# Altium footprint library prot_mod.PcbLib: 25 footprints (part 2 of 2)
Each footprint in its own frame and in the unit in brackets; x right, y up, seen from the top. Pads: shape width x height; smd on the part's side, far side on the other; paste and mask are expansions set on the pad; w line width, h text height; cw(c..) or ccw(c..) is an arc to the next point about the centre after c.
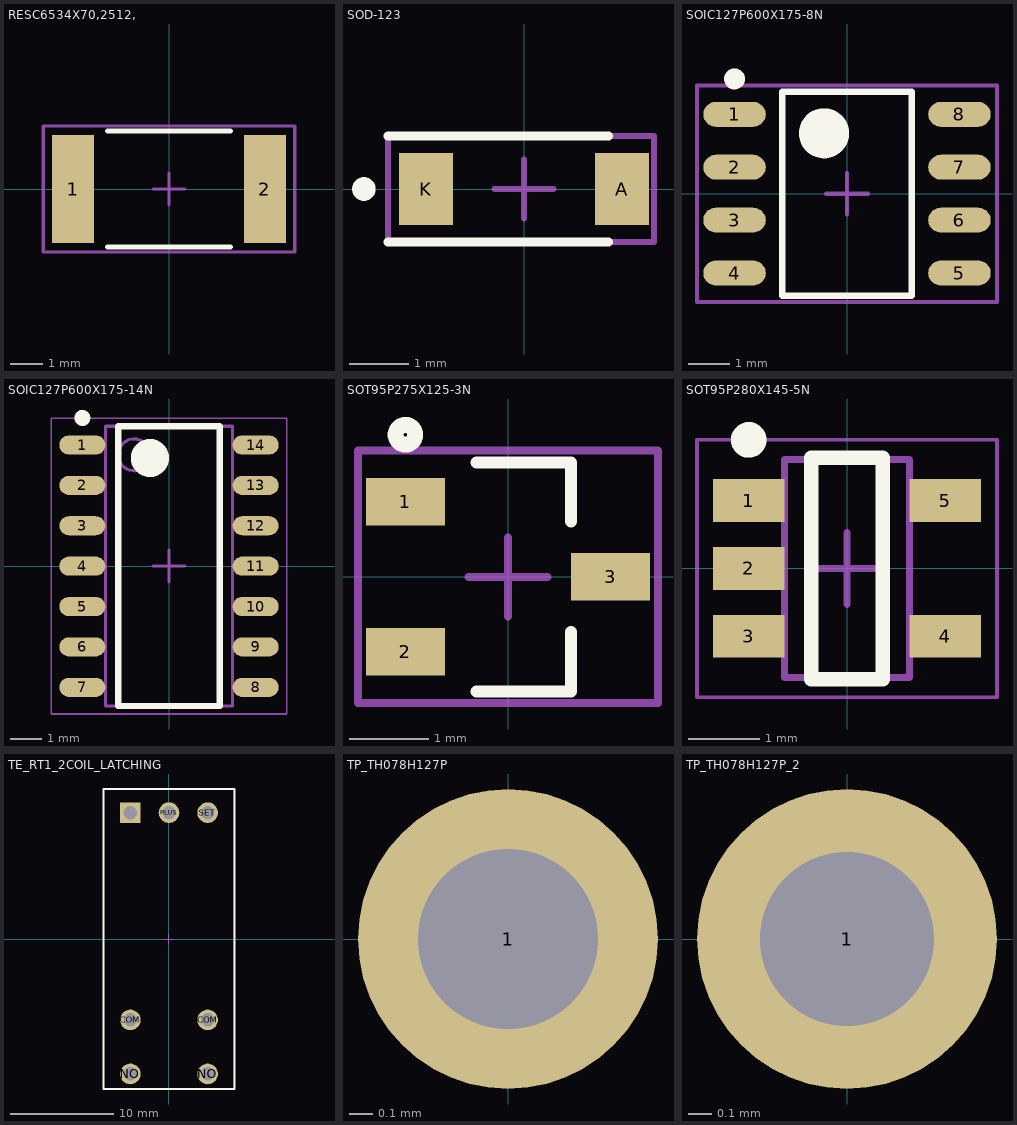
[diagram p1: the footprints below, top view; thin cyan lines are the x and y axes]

## RESC6534X70,2512, [mm]
pads (2):
  rect 1.3x3.35 smd: 1(-2.975,0) 2(2.975,0)
Top Overlay:
  lines w0.153: -1.9,-1.8 1.9,-1.8 ; -1.9,1.8 1.9,1.8
Top Component Center:
  lines w0.1: -0.5,0 0.5,0 ; 0,-0.5 0,0.5
Top Courtyard:
  lines w0.1: -3.9,-1.95 -3.9,1.95 3.9,1.95 3.9,-1.95 -3.9,-1.95
3D body: height 0.7, standoff 0, extent -2.65,-1.65 2.65,1.65
3D body: height 0.7, standoff 0, extent -3.25,-1.65 -2.65,1.65
3D body: height 0.7, standoff 0, extent 2.65,-1.65 3.25,1.65

## SOD-123 [mil]
pads (2):
  rect 36x48 smd: A(65.35,0) K(-65.35,0)
Top Overlay:
  circle w7.87: c-106.79,0 r3.94
  lines w6.02: -90.77,-35.43 56.3,-35.43 ; -90.77,35.43 56.3,35.43
Top Component Center:
  lines w3.94: -19.68,0 19.68,0 ; 0,-19.68 0,19.68
Top Courtyard:
  lines w3.94: -90.77,-35.43 86.61,-35.43 86.61,35.43 -90.77,35.43 -90.77,-35.43
3D body "SOD-123.STEP": height 53.19, standoff 0, extent -72.83,-31.49 72.84,31.5

## SOIC127P600X175-8N [mm]
pads (8):
  oval 1.5x0.6 smd: 1(-2.7,1.905) 2(-2.7,0.635) 3(-2.7,-0.635) 4(-2.7,-1.905) 5(2.7,-1.905) 6(2.7,-0.635) 7(2.7,0.635) 8(2.7,1.905)
Top Overlay:
  circle w0.25: c-2.7,2.755 r0.125
  circle w0.6: c-0.55,1.45 r0.3
  lines w0.153: -1.55,-2.45 -1.55,2.45 1.55,2.45 1.55,-2.45 -1.55,-2.45
Top Component Center:
  lines w0.1: -0.5,0 0.5,0 ; 0,-0.5 0,0.5
Top Courtyard:
  lines w0.1: -3.6,-2.6 -3.6,2.6 3.6,2.6 3.6,-2.6 -3.6,-2.6
3D body "SOIC127P600X175-8N.step": height 1.75, standoff 0, extent -3,-2.45 3,2.45

## SOIC127P600X175-14N [mm]
pads (14):
  oval 1.45x0.6 smd: 1(-2.725,3.81) 2(-2.725,2.54) 3(-2.725,1.27) 4(-2.725,0) 5(-2.725,-1.27) 6(-2.725,-2.54) 7(-2.725,-3.81) 8(2.725,-3.81) 9(2.725,-2.54) 10(2.725,-1.27) 11(2.725,0) 12(2.725,1.27) 13(2.725,2.54) 14(2.725,3.81)
Top Overlay:
  circle w0.6: c-0.6,3.4 r0.3
  circle w0.25: c-2.725,4.66 r0.125
  lines w0.2: -1.6,-4.4 1.6,-4.4 1.6,4.4 -1.6,4.4 -1.6,-4.4
Top Component Center:
  lines w0.1: -0.5,0 0.5,0 ; 0,-0.5 0,0.5
Top Assembly:
  circle w0.1: c-1.1,3.5 r0.5
  lines w0.1: -2,-4.4 2,-4.4 2,4.4 -2,4.4 -2,-4.4
Top Courtyard:
  lines w0.05: -3.7,-4.65 3.7,-4.65 3.7,4.65 -3.7,4.65 -3.7,-4.65
3D body: height 1.75, standoff 0.1, extent -2,-4.4 2,4.4

## SOT95P275X125-3N [mm]
pads (3):
  rect 1x0.6 smd: 1(-1.3,0.95) 2(-1.3,-0.95) 3(1.3,0)
Top Overlay:
  circle w0.2: c-1.3,1.8 r0.125
  lines w0.153: -0.4,-1.45 0.8,-1.45 0.8,-0.7 ; -0.4,1.45 0.8,1.45 0.8,0.7
Top Component Center:
  lines w0.1: -0.5,0 0.5,0 ; 0,-0.5 0,0.5
Top Courtyard:
  lines w0.1: -1.9,-1.6 1.9,-1.6 1.9,1.6 -1.9,1.6 -1.9,-1.6
3D body "SOT95P275X125-3N.step": height 1.25, standoff 0, extent -1.375,-1.45 1.375,1.45

## SOT95P280X145-5N [mm]
pads (5):
  rect 1x0.6 smd: 1(-1.375,0.95) 2(-1.375,0) 3(-1.375,-0.95) 4(1.375,-0.95) 5(1.375,0.95)
Top Overlay:
  circle w0.25: c-1.375,1.8 r0.125
  lines w0.2: -0.5,-1.55 -0.5,1.55 0.5,1.55 0.5,-1.55 -0.5,-1.55
Top Component Center:
  lines w0.1: -0.5,0 0.5,0 ; 0,-0.5 0,0.5
Top Assembly:
  lines w0.1: -0.875,-1.525 0.875,-1.525 0.875,1.525 -0.875,1.525 -0.875,-1.525
Top Courtyard:
  lines w0.05: -2.1,-1.8 2.1,-1.8 2.1,1.8 -2.1,1.8 -2.1,-1.8
3D body: height 1.45, standoff 0, extent -0.875,-1.525 0.875,1.525

## TE_RT1_2COIL_LATCHING [mm]
pads (7):
  round 2 hole 1.3: COM(-3.75,-7.85) COM(3.75,-7.85) NO(-3.75,-13.09) NO(3.75,-13.09) PLUS(0,12.25) SET(3.75,12.25)
  rect 2x2 hole 1.3: RESET(-3.75,12.25)
Top Overlay:
  lines w0.153: -6.35,-14.55 6.35,-14.55 6.35,14.55 -1.05,14.55 -6.35,14.55 -6.35,-14.55
Top Component Center:
  lines w0.1: -0.5,0 0.5,0 ; 0,-0.5 0,0.5
Top Courtyard:
  lines w0.1: -6.35,-14.55 -6.35,14.55 -1.05,14.55 6.35,14.55 6.35,-14.55 -6.35,-14.55
3D body: height 16, standoff 0, extent -6.35,-14.55 6.35,14.55
3D body: height 0, standoff -3.5, extent -4.25,11.75 -3.25,12.75
3D body: height 0, standoff -3.5, extent -0.5,11.75 0.5,12.75
3D body: height 0, standoff -3.5, extent 3.25,11.75 4.25,12.75
3D body: height 0, standoff -3.5, extent -4.25,-8.35 -3.25,-7.35
3D body: height 0, standoff -3.5, extent -4.25,-13.59 -3.25,-12.59
3D body: height 0, standoff -3.5, extent 3.25,-13.59 4.25,-12.59
3D body: height 0, standoff -3.5, extent 3.25,-8.35 4.25,-7.35

## TP_TH078H127P [mil]
pads (1):
  round 50 hole 30 mask+0: 1(0,0)

## TP_TH078H127P_2 [mil]
pads (1):
  round 50 hole 29 mask+0: 1(0,0)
